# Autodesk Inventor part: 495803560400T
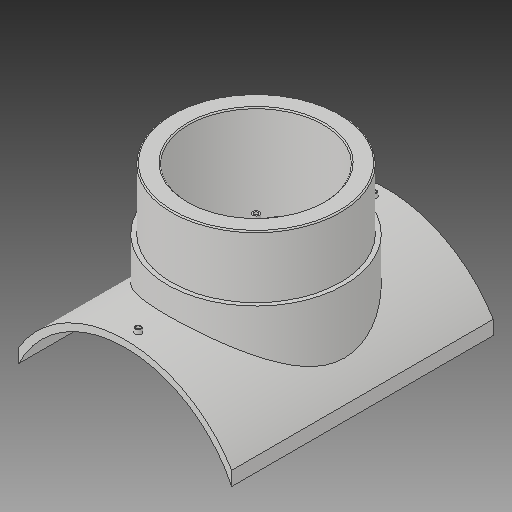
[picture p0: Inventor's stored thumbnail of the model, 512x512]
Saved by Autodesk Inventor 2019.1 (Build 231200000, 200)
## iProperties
Created: 2017-10
Part Number: 495803560400T
Material: Generic
Description: PLASSON BRANCH SADDLE 560x400
Document SubType Name: Modeling
Designer: KIM
Mass: 2754.05 g
Surface Area: 3037.44 cm^2
Volume: 2754.05 cm^3
Density: 1 g/cm^3
Appearance: Default
Author: KIM
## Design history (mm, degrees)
derived "495803.ipt"
feature "Solid1::495803.ipt"
tag "TaggingFeature1"
body "Solid1"
other parameters: "d1" = 16, "d2" = 505, "d4" = 0, "d12" = 305.6, "d13" = 14, "d14" = 279, "d16" = 5 deg, "d18" = 4, "d19" = 14, "d20" = 0, "d21" = 3, "d22" = 0, "d23" = 505, "d25" = 16, "d28" = 0, "d29" = 9.6, "d31" = 0, "d32" = 104.5, "d33" = 0, "d34" = 5.6, "d37" = 146.3, "d38" = 0, "d39" = 2.8, "B_" = 505, "H_" = 209, "x_" = 16, "D_" = 16
